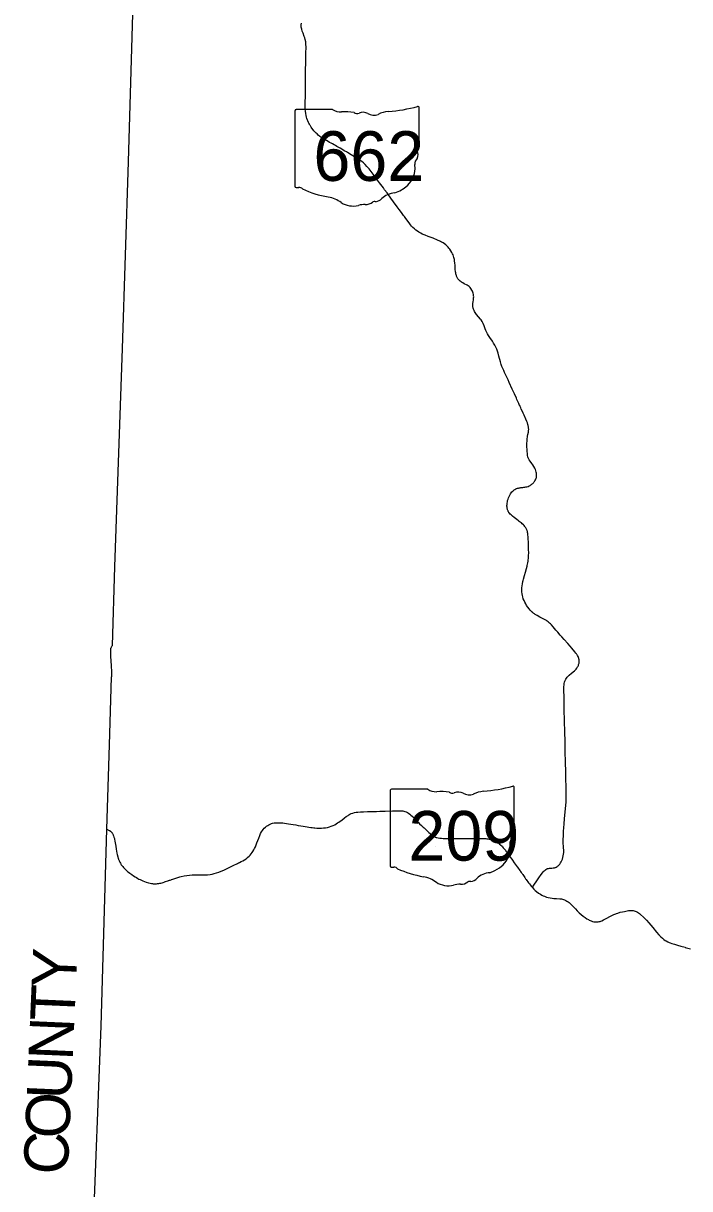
# Model space of a CAD drawing. Extents: x 1913970 to 2397567, y 78841 to 829347.
# Drawn here: x 2184600 to 2199640, y 744108 to 770418 of the extents above; entities that cross this region are included whole.
import ezdxf

# ---------------------------------------------------------------- set-up
doc = ezdxf.new("R2010")
doc.units = 0
for name, color, linetype in [('GM_X_County', 7, 'Continuous'), ('GM_X_County_Text', 7, 'Continuous'), ('GM_X_State_Location', 7, 'Continuous'), ('GM_X_State_Route', 7, 'Continuous'), ('GM_X_State_Shield', 7, 'Continuous')]:
    doc.layers.add(name, color=color, linetype=linetype)

msp = doc.modelspace()

# ---------------------------------------------------------------- linework, layer by layer
at = {"layer": 'GM_X_County'}
msp.add_lwpolyline([(2186166, 742913), (2186360, 747780), (2186483, 752225), (2186544, 754130), (2186591, 755654), (2186594, 755666), (2186595, 755674), (2186597, 755689), (2186599, 755724), (2186596, 755785), (2186589, 755903), (2186581, 756036), (2186578, 756115), (2186575, 756171), (2186574, 756216), (2186573, 756252), (2186574, 756272), (2186575, 756290), (2186578, 756306), (2186583, 756323), (2186588, 756336), (2186592, 756343), (2186599, 756355), (2186612, 756371), (2186663, 758149), (2186839, 763073), (2186978, 767293), (2187218, 775508)], dxfattribs=at)
at = {"layer": 'GM_X_State_Route'}
for points in [[(2191080, 768101), (2191073, 768113), (2191058, 768140), (2191045, 768167), (2191039, 768179), (2191023, 768215), (2191017, 768230), (2191003, 768268), (2190992, 768302), (2190982, 768339), (2190973, 768385), (2190966, 768433), (2190962, 768481), (2190961, 768524), (2190962, 768577), (2190965, 768661), (2190966, 768744), (2190968, 768830), (2190970, 768938), (2190970, 769016), (2190970, 769088), (2190972, 769156), (2190972, 769215), (2190972, 769268), (2190972, 769314), (2190972, 769350), (2190975, 769541), (2190976, 769593), (2190978, 769657), (2190977, 769717), (2190980, 769780), (2190981, 769844), (2190981, 769893), (2190980, 769936), (2190978, 769971), (2190973, 770002), (2190963, 770050), (2190952, 770088), (2190939, 770124), (2190914, 770192), (2190897, 770239), (2190884, 770284), (2190879, 770308), (2190875, 770332), (2190874, 770357), (2190875, 770387), (2190879, 770420)], [(2195881, 757837), (2195889, 757867), (2195913, 757948), (2195938, 758030), (2195958, 758106), (2195972, 758160), (2195976, 758180), (2195987, 758236), (2195994, 758275), (2195996, 758291), (2196002, 758349), (2196005, 758388), (2196006, 758408), (2196007, 758453), (2196006, 758545), (2196003, 758604), (2195999, 758711), (2195995, 758770), (2195992, 758835), (2195990, 758865), (2195986, 758901), (2195982, 758924), (2195977, 758945), (2195974, 758958), (2195969, 758970), (2195963, 758985), (2195957, 758997), (2195949, 759011), (2195939, 759029), (2195930, 759043), (2195918, 759058), (2195903, 759077), (2195886, 759096), (2195862, 759120), (2195841, 759138), (2195816, 759158), (2195795, 759174), (2195776, 759188), (2195736, 759218), (2195678, 759260), (2195639, 759291), (2195608, 759318), (2195587, 759338), (2195572, 759358), (2195562, 759370), (2195557, 759376), (2195551, 759386), (2195546, 759397), (2195540, 759410), (2195536, 759420), (2195531, 759435), (2195528, 759446), (2195524, 759465), (2195519, 759492), (2195517, 759517), (2195517, 759534), (2195518, 759554), (2195521, 759581), (2195525, 759613), (2195531, 759644), (2195541, 759678), (2195550, 759707), (2195565, 759737), (2195581, 759768), (2195595, 759792), (2195614, 759818), (2195630, 759838), (2195647, 759856), (2195656, 759865), (2195666, 759873), (2195681, 759885), (2195695, 759894), (2195714, 759905), (2195734, 759914), (2195757, 759921), (2195777, 759926), (2195794, 759929), (2195814, 759933), (2195833, 759936), (2195852, 759939), (2195875, 759940), (2195896, 759942), (2195920, 759946), (2195945, 759950), (2195967, 759956), (2195993, 759963), (2196018, 759974), (2196039, 759985), (2196058, 759997), (2196072, 760006), (2196086, 760018), (2196100, 760031), (2196113, 760042), (2196126, 760057), (2196136, 760072), (2196146, 760087), (2196160, 760110), (2196175, 760148), (2196180, 760166), (2196184, 760187), (2196185, 760199), (2196185, 760209), (2196185, 760234), (2196183, 760261), (2196177, 760287), (2196169, 760316), (2196159, 760343), (2196143, 760378), (2196123, 760412), (2196098, 760449), (2196075, 760480), (2196038, 760529), (2196016, 760565), (2195998, 760606), (2195991, 760632), (2195983, 760664), (2195977, 760709), (2195972, 760748), (2195969, 760796), (2195967, 760856), (2195967, 760930), (2195969, 760989), (2195972, 761025), (2195981, 761095), (2195988, 761132), (2196000, 761189), (2196006, 761229), (2196007, 761249), (2196005, 761285), (2196004, 761298), (2195997, 761336), (2195991, 761358), (2195979, 761396), (2195965, 761432), (2195943, 761478), (2195902, 761569), (2195880, 761617), (2195866, 761651), (2195840, 761707), (2195828, 761734), (2195813, 761765), (2195804, 761787), (2195801, 761793), (2195782, 761834), (2195767, 761866), (2195754, 761896), (2195742, 761923), (2195728, 761952), (2195683, 762054), (2195636, 762159), (2195568, 762308), (2195540, 762368), (2195518, 762412), (2195461, 762536), (2195442, 762577), (2195422, 762624), (2195404, 762668), (2195387, 762715), (2195369, 762773), (2195334, 762903), (2195315, 762970), (2195300, 763017), (2195284, 763063), (2195264, 763106), (2195240, 763153), (2195215, 763199), (2195190, 763240), (2195130, 763324), (2195100, 763369), (2195076, 763410), (2195056, 763450), (2195040, 763483), (2195025, 763519), (2194999, 763589), (2194977, 763641), (2194954, 763685), (2194932, 763721), (2194916, 763742), (2194876, 763790), (2194830, 763847), (2194797, 763890), (2194784, 763913), (2194774, 763932), (2194762, 763963), (2194755, 763986), (2194749, 764021), (2194746, 764057), (2194748, 764096), (2194753, 764131), (2194759, 764174), (2194764, 764219), (2194765, 764245), (2194764, 764268), (2194762, 764298), (2194756, 764322), (2194749, 764347), (2194739, 764374), (2194727, 764396), (2194704, 764432), (2194684, 764455), (2194664, 764475), (2194643, 764491), (2194618, 764506), (2194550, 764540), (2194518, 764557), (2194491, 764572), (2194479, 764580), (2194457, 764597), (2194442, 764609), (2194427, 764625), (2194411, 764646), (2194401, 764662), (2194391, 764683), (2194385, 764694), (2194381, 764707), (2194376, 764721), (2194371, 764739), (2194365, 764761), (2194361, 764781), (2194358, 764807), (2194351, 764866), (2194345, 764951), (2194340, 765007), (2194335, 765051), (2194329, 765088), (2194319, 765129), (2194309, 765164), (2194300, 765188), (2194290, 765211), (2194273, 765246), (2194252, 765283), (2194228, 765318), (2194207, 765344), (2194188, 765366), (2194162, 765393), (2194134, 765418), (2194105, 765439), (2194075, 765460), (2194049, 765475), (2194039, 765480), (2194016, 765492), (2194002, 765498), (2193946, 765524), (2193849, 765564), (2193741, 765605), (2193668, 765633), (2193606, 765660), (2193569, 765678), (2193530, 765701), (2193495, 765724), (2193463, 765749), (2193431, 765776), (2193395, 765808), (2193364, 765842), (2193338, 765872), (2193309, 765911), (2193236, 766009), (2193203, 766055), (2193184, 766082), (2193138, 766144), (2193087, 766214), (2193039, 766278), (2193000, 766330), (2192974, 766367), (2192942, 766409), (2192910, 766451), (2192810, 766589), (2192755, 766662), (2192728, 766701), (2192639, 766818), (2192596, 766876), (2192540, 766953), (2192518, 766983), (2192451, 767071), (2192404, 767130), (2192355, 767188), (2192313, 767232), (2192277, 767267), (2192239, 767299), (2192196, 767330), (2192152, 767360), (2192076, 767406), (2191999, 767450), (2191961, 767472), (2191929, 767491), (2191917, 767498), (2191891, 767513), (2191857, 767533), (2191820, 767555), (2191788, 767573), (2191751, 767596), (2191719, 767614), (2191679, 767637), (2191646, 767656), (2191613, 767675), (2191580, 767694), (2191547, 767712), (2191513, 767731), (2191478, 767751), (2191442, 767771), (2191409, 767790), (2191378, 767809), (2191348, 767827), (2191319, 767848), (2191293, 767866), (2191256, 767896), (2191229, 767920), (2191210, 767937), (2191181, 767966), (2191156, 767993), (2191140, 768014), (2191112, 768051), (2191095, 768077), (2191089, 768086), (2191080, 768101)], [(2196082, 750915), (2196088, 750921), (2196097, 750931), (2196106, 750941), (2196135, 750979), (2196172, 751033), (2196237, 751127), (2196290, 751202), (2196319, 751242), (2196338, 751265), (2196359, 751286), (2196377, 751301), (2196396, 751315), (2196416, 751327), (2196435, 751335), (2196448, 751339), (2196457, 751340), (2196473, 751343), (2196489, 751345), (2196504, 751345), (2196529, 751347), (2196556, 751349), (2196591, 751355), (2196606, 751360), (2196613, 751362), (2196626, 751368), (2196652, 751382), (2196660, 751388), (2196672, 751398), (2196686, 751410), (2196694, 751417), (2196708, 751434), (2196726, 751463), (2196741, 751489), (2196768, 751549), (2196780, 751586), (2196788, 751619), (2196794, 751657), (2196797, 751698), (2196797, 751744), (2196794, 751813), (2196788, 751934), (2196788, 752004), (2196789, 752061), (2196791, 752110), (2196796, 752178), (2196801, 752257), (2196809, 752343), (2196818, 752461), (2196826, 752542), (2196845, 752759), (2196850, 752840), (2196853, 752887), (2196854, 752935), (2196854, 752967), (2196855, 752996), (2196856, 753034), (2196855, 753086), (2196853, 753119), (2196850, 753201), (2196849, 753243), (2196847, 753302), (2196847, 753348), (2196847, 753407), (2196845, 753479), (2196844, 753561), (2196839, 753692), (2196835, 753817), (2196832, 753895), (2196830, 754063), (2196829, 754148), (2196827, 754243), (2196823, 754387), (2196821, 754462), (2196819, 754531), (2196818, 754557), (2196817, 754596), (2196816, 754639), (2196814, 754731), (2196811, 754865), (2196807, 755022), (2196806, 755121), (2196804, 755235), (2196802, 755331), (2196801, 755389), (2196803, 755442), (2196806, 755478), (2196810, 755514), (2196817, 755543), (2196825, 755568), (2196835, 755593), (2196846, 755614), (2196859, 755633), (2196876, 755654), (2196895, 755675), (2196921, 755700), (2196975, 755748), (2197037, 755801), (2197075, 755837), (2197096, 755861), (2197110, 755886), (2197121, 755906), (2197128, 755922), (2197133, 755940), (2197139, 755960), (2197143, 755976), (2197146, 755998), (2197146, 756013), (2197146, 756026), (2197144, 756047), (2197140, 756068), (2197137, 756082), (2197133, 756096), (2197128, 756107), (2197123, 756122), (2197112, 756142), (2197104, 756157), (2197096, 756169), (2197085, 756186), (2197074, 756199), (2197048, 756231), (2196981, 756309), (2196943, 756354), (2196887, 756418), (2196806, 756509), (2196752, 756569), (2196718, 756607), (2196663, 756672), (2196623, 756717), (2196562, 756789), (2196519, 756836), (2196498, 756858), (2196480, 756874), (2196443, 756906), (2196423, 756921), (2196409, 756932), (2196380, 756949), (2196346, 756967), (2196259, 757011), (2196196, 757045), (2196169, 757061), (2196152, 757072), (2196137, 757083), (2196124, 757092), (2196112, 757101), (2196099, 757112), (2196089, 757121), (2196082, 757127), (2196068, 757140), (2196043, 757166), (2196014, 757199), (2195985, 757238), (2195960, 757274), (2195939, 757310), (2195916, 757350), (2195901, 757384), (2195884, 757426), (2195872, 757467), (2195866, 757498), (2195859, 757541), (2195855, 757583), (2195855, 757625), (2195855, 757671), (2195859, 757716), (2195866, 757762), (2195875, 757813), (2195881, 757837)], [(2186484, 752222), (2186540, 752197), (2186546, 752194), (2186550, 752192), (2186555, 752188), (2186563, 752183), (2186570, 752177), (2186591, 752156), (2186604, 752141), (2186609, 752133), (2186615, 752123), (2186623, 752109), (2186628, 752098), (2186631, 752092), (2186636, 752077), (2186646, 752047), (2186655, 752013), (2186658, 751996), (2186666, 751953), (2186673, 751915), (2186679, 751875), (2186685, 751838), (2186696, 751770), (2186704, 751725), (2186713, 751683), (2186720, 751651), (2186733, 751600), (2186744, 751565), (2186748, 751552), (2186752, 751542), (2186756, 751532), (2186763, 751516), (2186767, 751506), (2186773, 751495), (2186781, 751477), (2186791, 751458), (2186799, 751443), (2186805, 751432), (2186812, 751423), (2186818, 751415), (2186827, 751401), (2186843, 751381), (2186860, 751361), (2186878, 751341), (2186891, 751327), (2186903, 751316), (2186917, 751303), (2186932, 751289), (2186952, 751272), (2186977, 751251), (2187001, 751233), (2187046, 751201), (2187086, 751173), (2187123, 751149), (2187154, 751130), (2187187, 751111), (2187211, 751098), (2187235, 751085), (2187264, 751072), (2187300, 751056), (2187334, 751042), (2187375, 751027), (2187423, 751013), (2187462, 751003), (2187492, 750998), (2187518, 750995), (2187531, 750993), (2187551, 750992), (2187562, 750992), (2187583, 750991), (2187607, 750993), (2187630, 750995), (2187656, 750999), (2187681, 751003), (2187701, 751007), (2187707, 751009), (2187735, 751016), (2187754, 751022), (2187776, 751029), (2187785, 751032), (2187813, 751041), (2187862, 751058), (2187878, 751063), (2187884, 751065), (2187899, 751070), (2187915, 751075), (2187936, 751083), (2187942, 751085), (2187976, 751096), (2188063, 751125), (2188135, 751148), (2188163, 751156), (2188234, 751171), (2188292, 751180), (2188350, 751188), (2188412, 751193), (2188477, 751196), (2188546, 751196), (2188694, 751194), (2188760, 751195), (2188816, 751201), (2188861, 751209), (2188906, 751220), (2188963, 751236), (2189013, 751253), (2189064, 751274), (2189124, 751301), (2189293, 751381), (2189369, 751419), (2189404, 751436), (2189436, 751452), (2189458, 751463), (2189478, 751472), (2189516, 751491), (2189554, 751511), (2189591, 751533), (2189607, 751543), (2189642, 751568), (2189670, 751592), (2189697, 751616), (2189720, 751640), (2189746, 751669), (2189766, 751696), (2189781, 751718), (2189803, 751755), (2189821, 751790), (2189839, 751829), (2189846, 751847), (2189874, 751913), (2189896, 751972), (2189914, 752021), (2189935, 752079), (2189957, 752126), (2189978, 752167), (2189997, 752195), (2190014, 752217), (2190040, 752246), (2190065, 752271), (2190088, 752289), (2190116, 752308), (2190139, 752323), (2190160, 752333), (2190175, 752340), (2190200, 752350), (2190227, 752358), (2190259, 752365), (2190292, 752370), (2190331, 752371), (2190368, 752371), (2190412, 752369), (2190458, 752364), (2190496, 752359), (2190538, 752354), (2190587, 752346), (2190639, 752338), (2190690, 752330), (2190752, 752320), (2190807, 752311), (2190861, 752302), (2190913, 752294), (2190958, 752286), (2191006, 752277), (2191048, 752270), (2191090, 752264), (2191123, 752259), (2191155, 752255), (2191179, 752252), (2191226, 752248), (2191254, 752247), (2191282, 752247), (2191327, 752248), (2191375, 752251), (2191421, 752257), (2191467, 752265), (2191510, 752276), (2191549, 752289), (2191591, 752306), (2191630, 752325), (2191665, 752344), (2191695, 752364), (2191725, 752385), (2191750, 752402), (2191755, 752406), (2191786, 752429), (2191847, 752477), (2191889, 752509), (2191929, 752535), (2191950, 752549), (2191969, 752560), (2191999, 752575), (2192037, 752589), (2192076, 752600), (2192111, 752606), (2192153, 752611), (2192208, 752615), (2192280, 752619), (2192371, 752622), (2192427, 752623), (2192502, 752625), (2192568, 752627), (2192646, 752629), (2192764, 752632), (2192934, 752638), (2193007, 752641), (2193046, 752641), (2193089, 752642), (2193123, 752642), (2193148, 752640), (2193165, 752638), (2193191, 752633), (2193213, 752626), (2193245, 752614), (2193274, 752598), (2193293, 752587), (2193323, 752566), (2193350, 752544), (2193377, 752520), (2193411, 752486), (2193445, 752450), (2193483, 752409), (2193500, 752391), (2193524, 752366), (2193545, 752346), (2193586, 752307), (2193627, 752270), (2193646, 752252), (2193702, 752201), (2193754, 752152), (2193785, 752123), (2193821, 752093), (2193839, 752080), (2193859, 752067), (2193878, 752057), (2193903, 752046), (2193919, 752040), (2193935, 752035), (2193964, 752028), (2194000, 752022), (2194039, 752018), (2194078, 752016), (2194124, 752015), (2194160, 752014), (2194193, 752013), (2194216, 752013), (2194268, 752013), (2194343, 752014), (2194409, 752016), (2194474, 752015), (2194533, 752015), (2194583, 752016), (2194625, 752016), (2194658, 752016), (2194681, 752016), (2194710, 752017), (2194727, 752017), (2194769, 752017), (2194802, 752017), (2194838, 752017), (2194870, 752017), (2194906, 752017), (2194922, 752016), (2194962, 752015), (2195010, 752014), (2195036, 752011), (2195062, 752009), (2195081, 752006), (2195112, 752000), (2195141, 751993), (2195160, 751988), (2195174, 751983), (2195190, 751977), (2195211, 751969), (2195244, 751954), (2195266, 751942), (2195294, 751927), (2195316, 751914), (2195336, 751900), (2195349, 751889), (2195374, 751869), (2195405, 751840), (2195419, 751823), (2195434, 751806), (2195465, 751768), (2195480, 751747), (2195492, 751731), (2195498, 751723), (2195506, 751713), (2195520, 751695), (2195530, 751682), (2195557, 751645), (2195592, 751594), (2195624, 751549), (2195641, 751525), (2195680, 751468), (2195723, 751406), (2195744, 751377), (2195754, 751364), (2195769, 751342), (2195793, 751311), (2195806, 751293), (2195819, 751274), (2195823, 751269), (2195840, 751245), (2195857, 751221), (2195868, 751205), (2195872, 751200), (2195887, 751178), (2195904, 751154), (2195917, 751135), (2195938, 751106), (2195951, 751088), (2195964, 751069), (2195968, 751063), (2195987, 751037), (2196006, 751010), (2196024, 750987), (2196044, 750961), (2196061, 750940), (2196082, 750915), (2196090, 750905), (2196121, 750871), (2196150, 750841), (2196181, 750814), (2196230, 750781), (2196257, 750764), (2196272, 750755), (2196307, 750735), (2196336, 750721), (2196362, 750710), (2196379, 750703), (2196407, 750693), (2196448, 750682), (2196492, 750671), (2196538, 750664), (2196572, 750661), (2196637, 750656), (2196708, 750653), (2196749, 750648), (2196772, 750643), (2196794, 750637), (2196816, 750628), (2196843, 750617), (2196871, 750602), (2196895, 750587), (2196918, 750569), (2196950, 750542), (2196973, 750518), (2196995, 750495), (2197060, 750425), (2197103, 750380), (2197146, 750339), (2197192, 750298), (2197236, 750263), (2197281, 750229), (2197322, 750201), (2197354, 750182), (2197374, 750171), (2197397, 750160), (2197415, 750153), (2197446, 750142), (2197475, 750134), (2197504, 750130), (2197529, 750129), (2197549, 750129), (2197572, 750132), (2197600, 750137), (2197621, 750143), (2197638, 750149), (2197659, 750158), (2197694, 750174), (2197740, 750197), (2197867, 750266), (2197927, 750295), (2197970, 750314), (2197985, 750319), (2198021, 750331), (2198075, 750348), (2198124, 750359), (2198168, 750369), (2198227, 750380), (2198262, 750385), (2198293, 750387), (2198328, 750387), (2198362, 750385), (2198385, 750380), (2198410, 750373), (2198434, 750364), (2198460, 750350), (2198488, 750335), (2198509, 750319), (2198533, 750299), (2198597, 750241), (2198627, 750210), (2198663, 750169), (2198718, 750107), (2198807, 750003), (2198894, 749900), (2198947, 749841), (2198990, 749794), (2199025, 749761), (2199056, 749735), (2199085, 749714), (2199106, 749700), (2199145, 749679), (2199181, 749663), (2199202, 749656), (2199236, 749643), (2199297, 749625), (2199369, 749604), (2199442, 749584), (2199537, 749558), (2199542, 749556), (2199662, 749521)]]:
    msp.add_lwpolyline(points, dxfattribs=at)
at = {"layer": 'GM_X_State_Shield'}
for p, q in [((2190732, 768442), (2190732, 766741)), ((2191580, 768471), (2190759, 768471)), ((2193534, 767623), (2193534, 768513)), ((2193533, 767624), (2193534, 767623)), ((2192881, 753096), (2192881, 751394)), ((2193729, 753125), (2192908, 753125)), ((2195682, 752277), (2195682, 753167)), ((2195682, 752277), (2195682, 752277))]:
    msp.add_line(p, q, dxfattribs=at)
for centre, major_axis, start_param, end_param in [((2192536, 770790), (2971, 0), 4.814394, 5.042369), ((2193502, 768517), (31.2, 0), 6.141152, 7.989035), ((2190764, 768446), (32.5, 0), 1.712693, 3.28349), ((2191775, 768669), (315, 0), 4.042523, 4.731795), ((2191880, 767516), (1130, 0), 1.404758, 1.657858), ((2192136, 768454), (90.8, 0), 3.836095, 5.185415), ((2192270, 768258), (189, 0), 0.950623, 2.079405), ((2192513, 768527), (227, 0), 4.081561, 5.145723), ((2192914, 767952), (598, 0), 1.699011, 2.107814), ((2193526, 767558), (48.3, 0), 1.883978, 3.671073), ((2193219, 767446), (290, 0), 5.934695, 6.695948), ((2193500, 767620), (33.4, 0), 5.05454, 6.418171), ((2192702, 767138), (743, 0), 5.101752, 6.440018), ((2193645, 767251), (211, 0), 2.387724, 3.262537), ((2190764, 766737), (32.7, 0), 3.00124, 4.508301), ((2190769, 766911), (250, 0), 4.665946, 4.897461), ((2190820, 766643), (90.1, 0), 0.519207, 1.627899), ((2191958, 768171), (2146, 0), 4.195997, 4.488961), ((2191318, 765976), (671, 0), 0.823519, 1.323587), ((2192500, 766576), (240, 0), 4.937069, 5.64225), ((2193015, 766263), (407, 0), 1.647645, 2.488434), ((2192044, 766634), (426, 0), 4.026481, 4.996735), ((2192290, 766046), (350, 0), 1.495662, 1.94098), ((2192322, 766507), (227, 0), 4.691044, 5.507374), ((2192527, 766342), (63.9, 0), 1.147584, 2.315152), ((2192913, 753099), (32.5, 0), 1.712693, 3.28349), ((2193924, 753322), (315, 0), 4.042523, 4.731795), ((2194029, 752170), (1130, 0), 1.404758, 1.657858), ((2194285, 753108), (90.8, 0), 3.836095, 5.185415), ((2194418, 752911), (189, 0), 0.950623, 2.079405), ((2194662, 753181), (227, 0), 4.081561, 5.145723), ((2195063, 752605), (598, 0), 1.699011, 2.107814), ((2194684, 755444), (2971, 0), 4.814394, 5.042369), ((2195651, 753171), (31.2, 0), 6.141152, 7.989035), ((2195675, 752212), (48.3, 0), 1.883978, 3.671073), ((2195649, 752274), (33.4, 0), 5.05454, 6.418171), ((2195794, 751905), (211, 0), 2.387724, 3.262537), ((2195368, 752099), (290, 0), 5.934695, 6.695948), ((2194851, 751792), (743, 0), 5.101752, 6.440018), ((2192913, 751391), (32.7, 0), 3.00124, 4.508301), ((2192918, 751565), (250, 0), 4.665946, 4.897461), ((2192969, 751296), (90.1, 0), 0.519207, 1.627899), ((2194107, 752825), (2146, 0), 4.195997, 4.488961), ((2195164, 750917), (407, 0), 1.647645, 2.488434), ((2193467, 750630), (671, 0), 0.823519, 1.323587), ((2194193, 751288), (426, 0), 4.026481, 4.996735), ((2194439, 750700), (350, 0), 1.495662, 1.94098), ((2194470, 751161), (227, 0), 4.691044, 5.507374), ((2194676, 750996), (63.9, 0), 1.147584, 2.315152), ((2194648, 751230), (240, 0), 4.937069, 5.64225)]:
    msp.add_ellipse(centre, major_axis=major_axis, ratio=0.8, start_param=start_param, end_param=end_param, dxfattribs=at)

# ---------------------------------------------------------------- texts
at = {"layer": 'GM_X_County_Text'}
for s, rotation, p in [('Y', 87.501, (2185785, 748623)), ('T', 87.4973, (2185752, 747875)), ('N', 87.5004, (2185713, 746992)), ('U', 87.501, (2185675, 746108)), ('O', 87.4982, (2185636, 745225)), ('C', 87.5111, (2185601, 744411))]:
    msp.add_text(s, height=1000, rotation=rotation, dxfattribs=at).set_placement(p)
at = {"layer": 'GM_X_State_Location'}
msp.add_text('209', height=1, rotation=0, dxfattribs=at).set_placement((2193910, 751825))
for s in ['s', 'r']:
    msp.add_text(s, height=1, dxfattribs=at).set_placement((2194263, 751898))
at = {"layer": 'GM_X_State_Shield'}
for s, p in [('662', (2191148, 766861)), ('209', (2193293, 751514))]:
    msp.add_text(s, height=1120.7, dxfattribs=at).set_placement(p)

doc.saveas('drawing.dxf')
